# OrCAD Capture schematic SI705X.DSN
size B; title: Si705X postage stamp; rev: 1.0
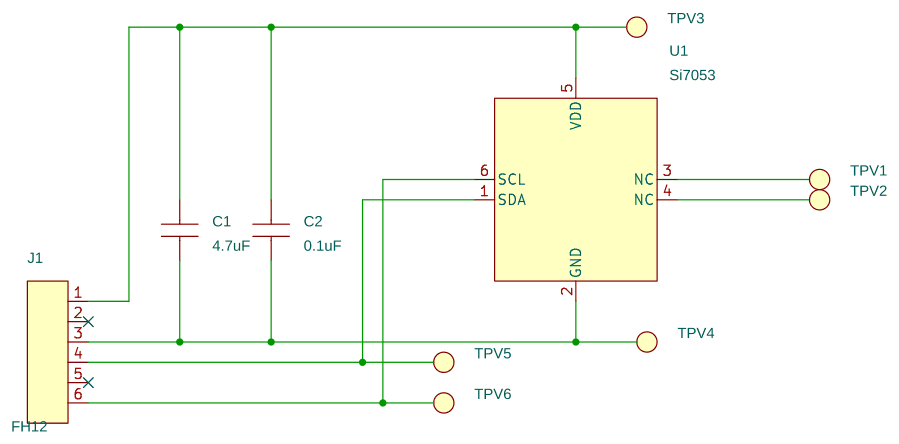
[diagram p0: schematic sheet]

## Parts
C1  4.7uF  [C0603]
C2  0.1uF  [C0402]
J1  FH12  [CONN6N-FPC/FFC-P0.5]
TPV1  TPV  [VIA-TP]
TPV2  TPV  [VIA-TP]
TPV3  TPV  [VIA-TP]
TPV4  TPV  [VIA-TP]
TPV5  TPV  [VIA-TP]
TPV6  TPV  [VIA-TP]
U1  Si7053  [DFN6M3X3P1.0E]

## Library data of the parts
C1 = CAP_NP: CAP, 4.7uF, 6.3V, ±10%, X5R, 0603; Manufacturer: Venkel; ManufacturerPN: C0603X5R6R3-475K; Part_Type: CAP/NP; SiLabsPN: C0603X5R6R3-475K; Tolerance: ±10%; Type: X5R; Voltage: 6.3V; Datasheet: PID_C.pdf
C2 = CAP_NP: CAP, 0.1uF, 10V, ±10%, X7R, 0402; Manufacturer: Venkel; ManufacturerPN: C0402X7R100-104K; Part_Type: CAP/NP; SiLabsPN: C0402X7R100-104K; Tolerance: ±10%; Type: X7R; Voltage: 10V; Datasheet: PID_C.pdf
J1 = CON6: CONN, 6-PIN , FPC/FFC, BOTTOM CONTACT, 0.5MM PITCH, SMD; Manufacturer: HIROSE; ManufacturerPN: FH12-6S-0.5SH(55); Part_Type: CON/MODULAR; SiLabsPN: FH12-6S-0.5SH(55); Datasheet: e58605370.pdf
TPV1-TPV6 = TPV: TESTPOINT Via; Manufacturer: N/A; ManufacturerPN: N/A; Type: PCB Feature
U1 = Si705x: IC, Temperature Sensor, ±0.3°C, -10 to +85°C, DFN6; Manufacturer: SiLabs; ManufacturerPN: Si7053-A10-IM; SiLabsPN: Si7053-A10-IM; Type: Temperature; Datasheet: Si705x-short.pdf

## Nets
N16774627: C1.1 C2.1 J1.3 TPV4.1(Point) U1.2(GND)
N16774631: C1.2 C2.2 J1.1 TPV3.1(Point) U1.5(VDD)
N16774635: TPV1.1(Point) U1.3(NC)
N16774639: TPV2.1(Point) U1.4(NC)
N16774711: J1.4 TPV5.1(Point) U1.1(SDA)
N16774715: J1.6 TPV6.1(Point) U1.6(SCL)

Not connected (* = marked no-connect by the designer): J1 2* 5*
